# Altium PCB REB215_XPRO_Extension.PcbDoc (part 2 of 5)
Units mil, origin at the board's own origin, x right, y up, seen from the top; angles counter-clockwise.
Board outline 4055.74 x 2606 mil, 6 copper layers (Top Layer LF-signals, Signal Layer 1, Internal Plane 1, Mid-1, Mid-2, Bottom Layer LF-signals), stack 58.434 mil thick; 278 components, 292 nets, 1282 pads, 1177 vias.
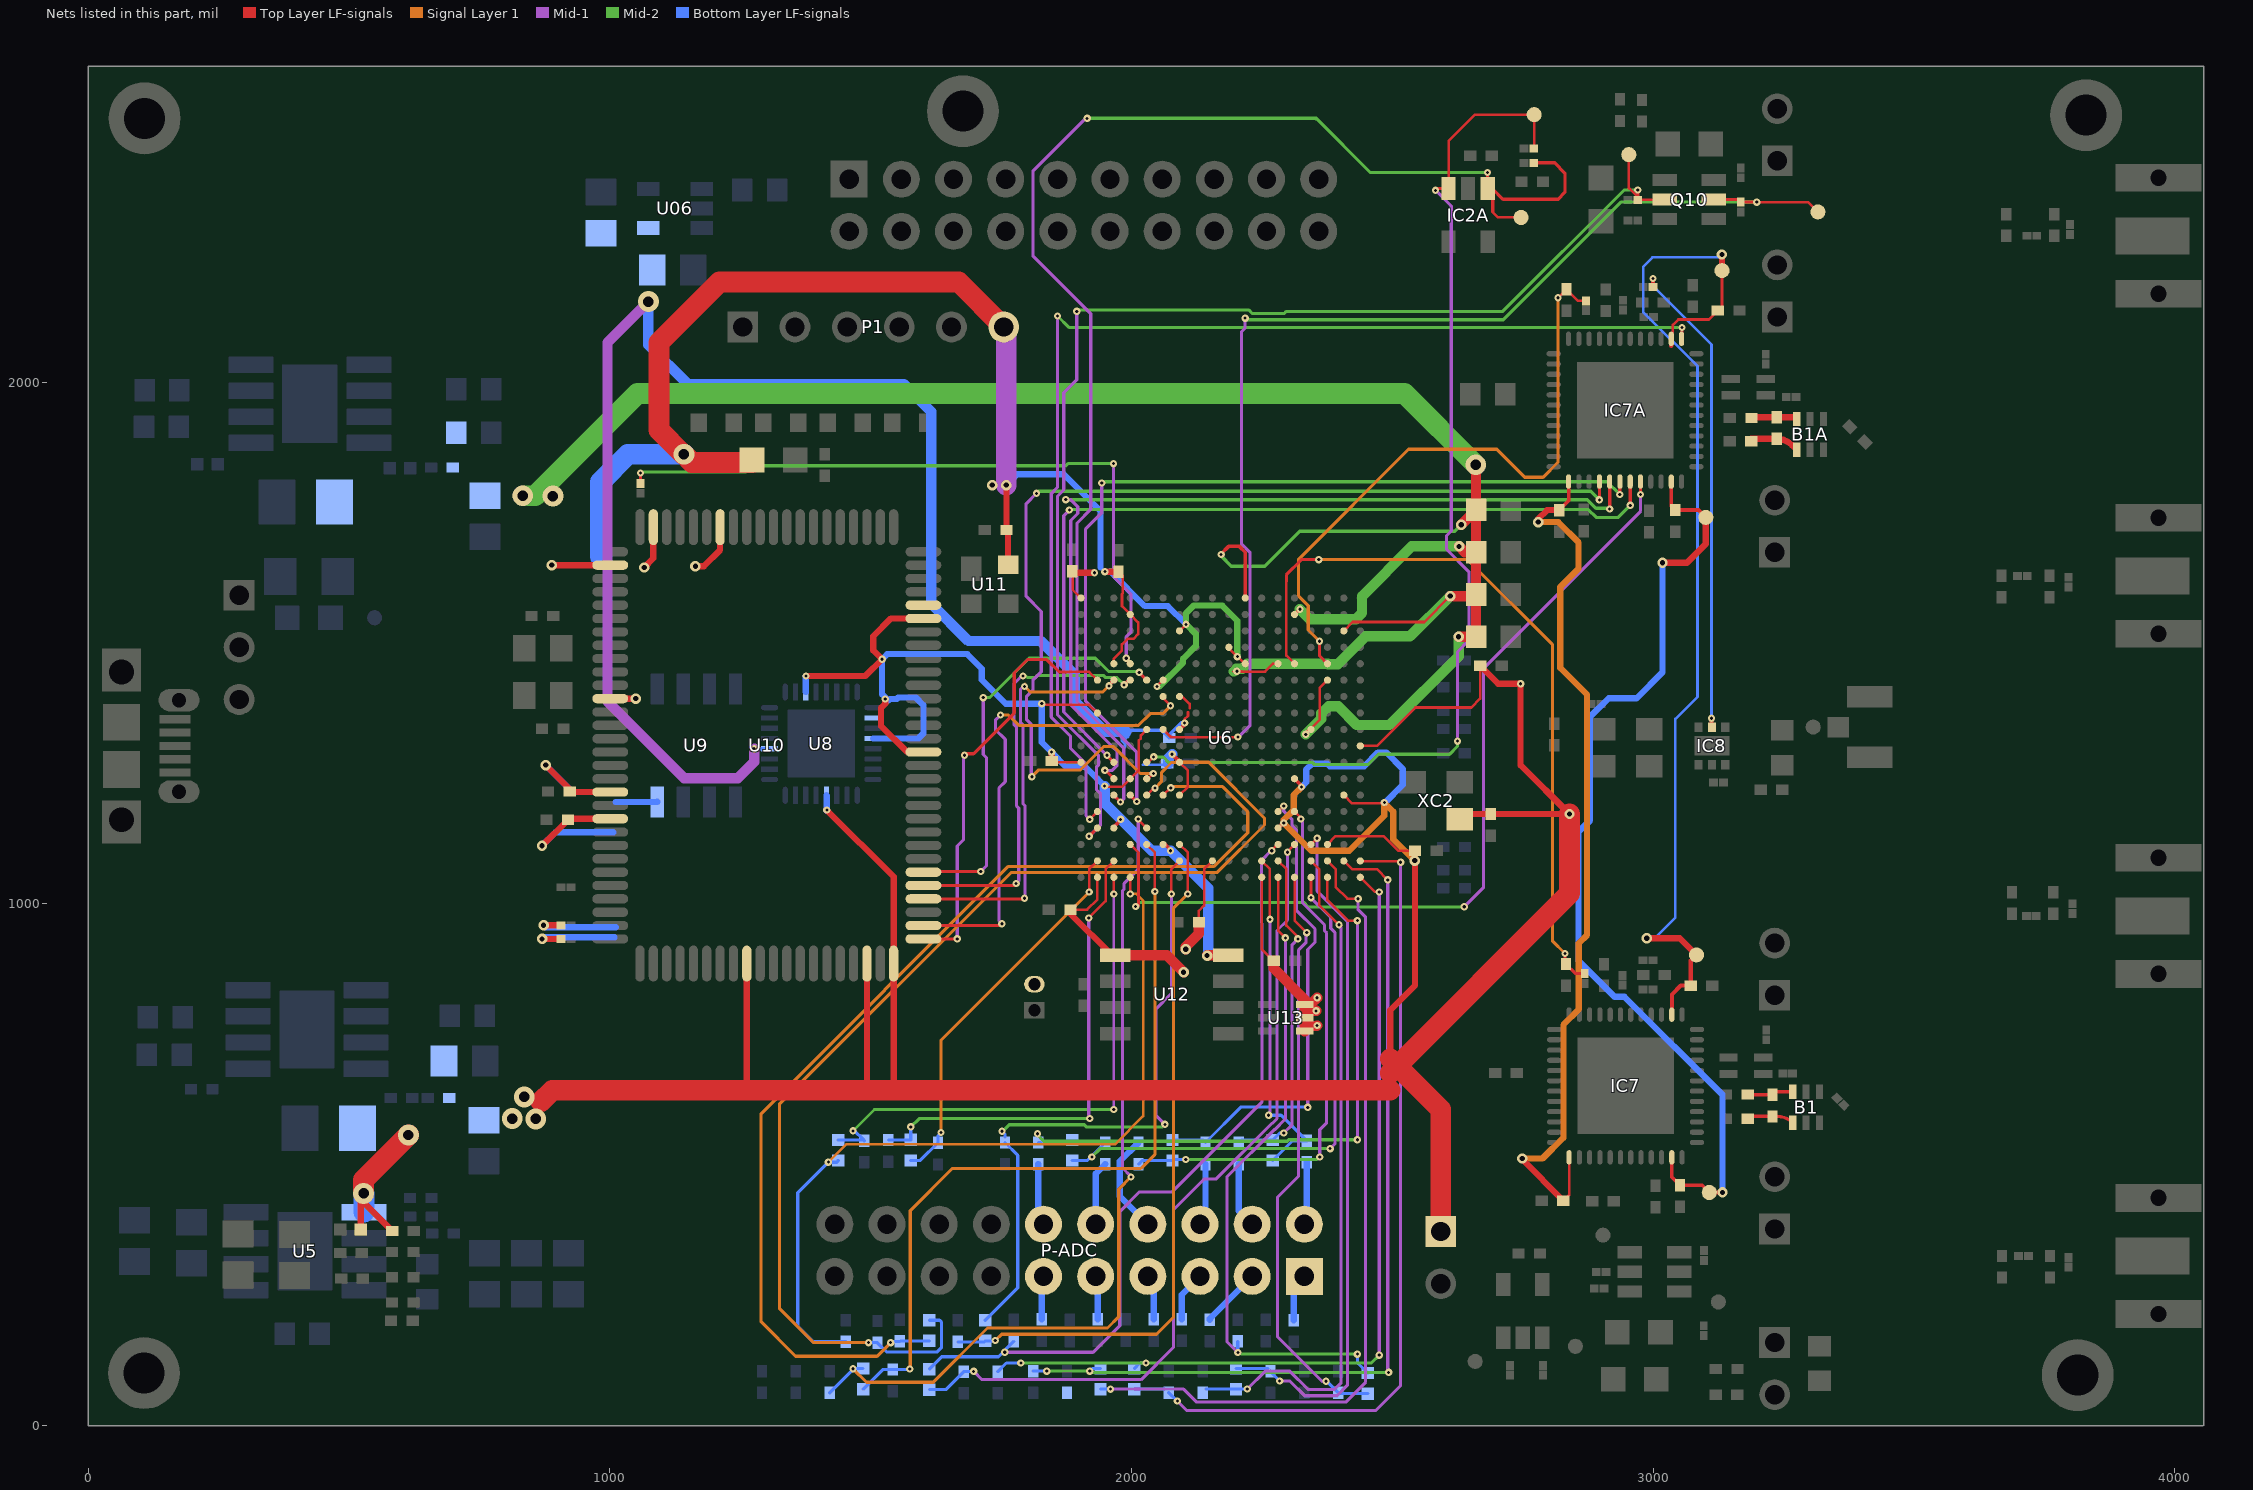
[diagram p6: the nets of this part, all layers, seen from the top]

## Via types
v1: diameter 20, hole 10, Top Layer LF-signals to Bottom Layer LF-signals, 660 vias
v2: diameter 14, hole 6, Top Layer LF-signals to Bottom Layer LF-signals, 470 vias
v3: diameter 40, hole 20, Top Layer LF-signals to Bottom Layer LF-signals, 46 vias
v4: diameter 12, hole 6, Top Layer LF-signals to Bottom Layer LF-signals, 1 vias

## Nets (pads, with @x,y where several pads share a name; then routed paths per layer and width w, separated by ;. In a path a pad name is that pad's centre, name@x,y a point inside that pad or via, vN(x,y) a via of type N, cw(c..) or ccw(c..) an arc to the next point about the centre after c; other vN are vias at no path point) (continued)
1V8: C48.1 C53.1 C54.1 L8.2 U06.4 U6.F12 U6.H12 U6.K12 U6.M12 U8.20 | length 3180.8
  Top Layer LF-signals w5: U6.F12@2092.18,1208.54 2107.93,1224.28 2107.93,1255.78 U6.H12@2092.18,1271.53 ; U6.M12@2092.18,1397.51 2097.28,1397.51 2111.41,1383.38 2111.41,1375.38 ; v2(2102,1347) 2102,1354.21 2108.38,1360.59 2108.38,1367.59
  Top Layer LF-signals w8: v2(2078,1287) 2092.18,1272.82 U6.H12@2092.18,1271.53 ; U6.K12@2092.18,1334.52 2102,1344.34 v2(2102,1347)
  Mid-1 w20: v3(1074,2154.53) 995.51,2076.04 995.51,1388.22 1142.57,1241.16 1245.34,1241.16 1276.67,1272.49 v2(1276.67,1297.46)
  Bottom Layer LF-signals w5: 1981.71,1319 1981.71,1312.49 1987.87,1306.33 ; 2022.2,1266.6 2068.66,1266.6 C53.1@2068.66,1269
  Bottom Layer LF-signals w6: v2(1276.67,1297.46) U8.20@1306.35,1297.46 ; 1987.87,1300.92 1987.87,1317.3 1992.99,1322.42 ; 1992.99,1319.93 1992.99,1322.42 ; 1996.05,1325.48 1992.99,1322.42 ; C53.1@2068.66,1266.1 C53.1@2068.66,1266.6 ; C54.1@2072.23,1318 2057.32,1332.91 1992.99,1332.91 1992.99,1322.42
  Bottom Layer LF-signals w7: C54.1@2072.46,1324.16 2095.3,1347 v2(2102,1347)
  Bottom Layer LF-signals w20: v3(1074,2154.53) 1074,2071.79 1149.08,1996.71 1563.07,1996.71 1616.09,1943.7 1616.09,1575.52 1687.58,1504.03 1826.41,1504.03 1890.92,1439.52 1890.92,1388.8 1949.45,1330.27 1989.78,1330.27 ; C53.1@2070.66,1269 2070.66,1279.66 v2(2078,1287)
2V5: C34.1 C35.1 C79.1 C80.1 C81.1 C82.1 L5.2 R18.2 U6.K4 U6.N3 U6.P6 U6.T2 U6.U5 U6.V8 | length 4925.4
  Top Layer LF-signals w5: v2@2195.67,1445.52 2211.51,1445.52 2211.83,1445.21 2255.99,1445.21 2271.29,1460.5 U6.P6@2281.15,1460.5 ; U6.K4@2342.01,1334.52 2361.25,1353.76 2361.25,1414.62 U6.N3@2375.64,1429.01 ; U6.T2@2407.14,1523.5 2424.14,1540.5 2561.45,1540.5 v1(2611,1590.05) ; v1@2629.03,1729.97 v1(2632,1727) 2632,1727.1 C79.1@2660.54,1755.63
  Top Layer LF-signals w7: v2(2172,1670) 2172,1671.2 2186.21,1685.41 2207.01,1685.41 2218.16,1674.25 U6.V8@2218.16,1586.49 ; U6.U5@2312.65,1554.99 2322.66,1565 v2(2323,1565) ; v2@2333,1325 v2(2334,1325) 2334,1326.51 2342.01,1334.52 U6.K4@2344.15,1334.52
  Top Layer LF-signals w20: v1(2611,1590.05) 2657.37,1590.05 C82.1@2660.54,1593.21 ; v1(2627,1512) C80.1@2660.54,1512 ; v1(2628,1685.45) 2639.03,1674.42 C81.1@2660.54,1674.42 ; v1(2632,1727) C79.1@2660.54,1755.54 ; C80.1@2658.54,1510 C80.1@2660.54,1512 ; v3(2660,1842) 2660,1846.93 2660.54,1847.47 C79.1@2660.54,1755.63 C79.1@2660.54,1755.54 ; C80.1@2660.54,1512 C82.1@2660.54,1593.21 ; C82.1@2660.54,1593.21 C81.1@2660.54,1674.42 ; C81.1@2660.54,1674.42 C79.1@2660.54,1755.54
  Mid-2 w7: v2(2172,1670) 2172,1666.8 2191.32,1647.48 2255.48,1647.48 2322.66,1714.66 2619.66,1714.66 v1(2632,1727) ; 2492,1340 2495,1343
  Mid-2 w20: v2@2195.67,1445.52 2201.24,1451.1 2212.49,1451.1 2221.9,1460.5 2376.03,1460.5 2377.39,1459.14 2395.62,1459.14 2449.48,1513 2533.95,1513 v1(2611,1590.05) ; v2(2323,1565) 2342,1546 2429.64,1546 2442,1558.36 2442,1577.23 2441.88,1577.35 2441.88,1589.77 2442,1589.89 2442,1590 2537.45,1685.45 v1(2628,1685.45) ; v2(2334,1325) 2334.11,1325 2364.16,1355.05 2364.16,1365.27 2377.89,1379 2396.11,1379 2432.11,1343 2495,1343 2627,1475 v1(2627,1512)
  Mid-2 w40: v3(833,1782.37) 856.37,1782.37 1052.85,1978.85 2523.15,1978.85 v3(2660,1842)
  other v2: 2202,1446
  other v3: 891,1781.78
3V3: C29.1 C30.1 C65.1 C66.1 C67.1 C68.1 C69.1 C70.1 C71.1 C72.1 C73.1 C74.1 C75.1 C76.1 D2A1.1 JP.1 L4.2 P1.6 P4.2 R001.2 R002.2 R015.2 R26.1 R27.1 U5.5 U6.A7 U6.A17 U6.B10 U6.C3 U6.C13 U6.D6 U6.D16 U6.F2 U6.G5 U6.G15 U6.H18 U6.J1 U6.K14 U6.L17 U6.N13 U6.P8 U6.P16 U6.R9 U6.T12 U6.U15 U6.V18 U8.4 U8.12 U8.27 U9.8 U10.2 U10.12 U10.19 U10.21 U10.39 U10.48 U10.50 U10.65 U10.75 U10.94 U10.99 U11.4 U12.1 U12.8 U13.4 U13.5 U13.6 XC2.4 | length 14448.6
  Top Layer LF-signals w5: v2@1826,1379.83 1827.93,1381.76 1918.95,1381.76 U6.L17@1934.7,1366.02 ; v2@1847,1291.58 v2(1847,1291) 1847.34,1290.66 1847.42,1290.58 1847.42,1274.08 C73.1@1847.34,1274 ; C73.1@1849.81,1271.53 U6.H18@1903.2,1271.53 ; C72.1@1883,989 1915,989 1934.7,1008.7 U6.A17@1934.7,1051.06 ; C74.1@1887.45,1636.94 1887.45,1602.24 U6.V18@1903.2,1586.49 ; v2(1948.59,1225.93) 1949.78,1224.74 1982.39,1224.74 U6.G15@1997.69,1240.03 2013.89,1256.23 2013.89,1312.89 2018,1317 2018,1323.33 U6.K14@2029.19,1334.52 ; U6.P16@1966.19,1460.5 1966.19,1470.37 1981.49,1485.66 1981.49,1497.43 1992.26,1508.2 2004.03,1508.2 2012.98,1517.16 2012.98,1539.7 U6.U15@1997.69,1554.99 1981.94,1570.74 1981.94,1594.16 1983.41,1595.62 1983.41,1628.26 C75.1@1975,1636.66 ; v2(2049,1417) 2049,1417.33 U6.N13@2060.68,1429.01 ; U6.T12@2092.18,1523.5 v2(2104.68,1536) ; C71.1@2129.34,965 2129.34,986.93 2139.42,997.01 2139.42,1066.8 U6.B10@2155.17,1082.55 ; v1(2145,901) v1@2145.45,901.45 ; U6.R9@2186.67,1492 2186.67,1490.08 2216.24,1460.5 U6.P8@2218.16,1460.5 ; U6.A7@2249.66,1051.06 2249.66,914 C68.1@2272.66,891 ; U6.C3@2375.64,1114.05 2391.39,1129.8 2483.56,1129.8 2511.26,1102.09 C76.1@2543.66,1102.09 ; U6.F2@2407.14,1208.54 2422.89,1192.79 2483.18,1192.79 v2(2484.72,1194.33) v2@2485,1194.61 ; U6.J1@2438.63,1303.02 2470.52,1303.02 2544.1,1376.6 2651.62,1376.6 2668.5,1393.47 C66.1@2668.5,1456.5
  Top Layer LF-signals w7: U6.D16@1966.19,1145.54 1966.19,1147.69 1979.22,1160.72 v2(1979.22,1162.07) ; U6.C13@2060.68,1114.05 2064.95,1114.05 2075,1104 v2(2075,1102) v2@2075.43,1102 ; U6.D6@2281.15,1145.54 2290.61,1155 v2(2292,1155) ; U6.G5@2312.65,1240.03 2326,1226.68 v2(2326,1224)
  Top Layer LF-signals w12: R26.1@522.69,376 v3@522.69,439.69 ; v3(528,445) 528,427.66 R27.1@582.66,373 ; v1(870,1111.63) C69.1@920,1161.63 ; v1(870.06,933) R002.2@906.65,933 ; v1(873,959) R001.2@906.65,959 ; v1(877,1266.1) 923,1220.1 C67.1@923,1215.4 ; v1@887.91,1648.5 v1(888.88,1649.47) U10.2@1000.8,1649.47 ; C69.1@921.62,1163.25 U10.21@1000.8,1163.25 ; C67.1@923.97,1214.43 U10.19@1000.8,1214.43 ; U10.12@1000.8,1393.57 v1(1049.57,1393.57) ; v1(1066,1645) 1083.48,1662.48 U10.99@1083.48,1722.31 ; v1(1164,1647.48) 1180.48,1647.48 1211.43,1678.43 U10.94@1211.43,1722.31 ; 1262.61,642.91 U10.39@1262.61,885.69 ; v2(1376,1437) 1490,1437 v2(1522,1469) 1505,1486 1505,1513.28 1538.83,1547.11 U10.75@1601.2,1547.11 ; v2(1416,1180) 1544.11,1051.89 U10.50@1544.11,885.69 1544.11,644.8 ; 1492.93,648.98 U10.48@1492.93,885.69 ; v2(1528,1393) 1528,1384 1520,1376 1520,1341 1569.8,1291.21 U10.65@1601.2,1291.21 ; v1@1757.44,1800.44 v1(1760,1803) 1760.34,1802.66 C65.1@1760.34,1716.79 ; U11.4@1763.43,1650.4 C65.1@1763.43,1713.7 ; C73.1@1847.34,1274 v2@1847.34,1290.66 ; C72.1@1883,989 1883,981.26 1962.81,901.45 U12.1@1968.83,901.45 ; C74.1@1886.73,1637.66 1884.07,1635 v2(1929,1635) ; v2@1949.09,1637.1 v2(1949,1637) 1949.34,1636.66 C75.1@1975,1636.66 ; 2496.09,676.1 2496.09,796.45 2543.66,844.02 C76.1@2543.66,1102.09 ; XC2.4@2639.05,1172.34 C70.1@2689,1172.34 v1(2839.66,1172.34) ; C66.1@2668.5,1456.5 2702.82,1422.18 v2(2746,1422.18) 2746,1266 v1(2839.66,1172.34) ; v1@2841,1171 v1(2839.66,1172.34)
  Top Layer LF-signals w20: U12.1@1968.83,901.45 2067.55,901.45 v1(2100,869) ; v1(2104,913) 2104,917.74 2129.34,943.08 C71.1@2129.34,965 ; v1@2145.45,901.45 U12.8@2185.36,901.45 ; C68.1@2272.66,891 2272.66,876.34 2332.36,816.64 U13.6@2332.36,807.36 ; U13.4@2332.36,756.18 2332.36,766 ; v2(2354,795) 2332.36,795 ; v2(2356,767) 2355,766 2332.36,766 ; v2(2356,820.2) 2343.16,807.36 U13.6@2332.36,807.36 ; 2332.36,766 U13.5@2332.36,781.77 2332.36,795 ; 2332.36,795 U13.6@2332.36,807.36
  Top Layer LF-signals w40: v3(528,445) 528,471 v3(614,557) ; 868,621 889.91,642.91 1262.61,642.91 2496.09,642.91 ; D2A1.1@1272.66,1851 1272.66,1846.51 1157.49,1846.51 v3(1142,1862) 1140.47,1862 1094,1908.47 1094,2076 1210,2192 1669,2192 P1.6@1755,2106 ; 2496.09,676.1 2839.66,1019.66 v1(2839.66,1172.34) ; 2496.09,703.1 2593,606.19 JP.1@2593,372
  Mid-1 w40: v1(1760,1803) P1.6@1760,2101
  Mid-2 w6: v2(2049,1417) v2@2053.74,1417
  Mid-2 w12: v2@2053.74,1417 2098.91,1462.17 2098.91,1470.22 2123.67,1494.99 2123.67,1517.01 v2(2104.68,1536) 2104.68,1557.78 2118.91,1572 2174,1572 2203,1543 v2(2203,1474)
  Signal Layer 1 w12: v2(2326,1224) 2310.91,1208.91 2310.91,1180.06 2292,1161.15 v2(2292,1155) 2345,1102 2417.54,1102 2484.72,1169.19 v2(2484.72,1194.33) 2502,1177.06 2502,1124 v1(2543,1083)
  Bottom Layer LF-signals w12: v3(528,445) 528,409.84 U5.5@528.66,409.18 ; v1(870,1111.63) 896.03,1137.66 1006.34,1137.66 ; v1(870.06,933) 872.97,935.91 1008.91,935.91 ; v1(873,959) 876.79,955.21 1011.21,955.21 ; v1(877,1266.1) 928.67,1214.43 1000.8,1214.43 ; 1011.54,1195.47 U9.8@1091,1195.47 U9.8@1091,1196 ; U8.27@1375.8,1406.31 1375.8,1436.8 v2(1376,1437) ; U8.12@1415.2,1208.31 1416,1207.51 v2(1416,1180) v2@1416,1178.4 ; U8.4@1504.35,1317.16 1591.65,1317.16 1601.2,1326.7 1601.2,1380.71 1586,1395.91 1553.17,1395.91 1550.26,1393 1537,1393 1534,1390 1522,1402 v2(1522,1469) 1532,1479 1685,1479 1713,1451 1713,1430 1759,1384 v2(1828,1384) 1828,1310 v2(1847,1291) 1847,1290.26 1874.26,1263 1911.52,1263 v2(1948.59,1225.93) ; v1(1760,1803) 1780.91,1823.91 1870.14,1823.91 1940.55,1753.5 1940.55,1645 ; 1958,1636.66 1960.08,1636.66 2025.74,1571 2069.68,1571 v2(2104.68,1536) ; v2(2326,1224) 2335.21,1233.21 2335.21,1257.83 2346.28,1268.91 2375.36,1268.91 2380.17,1264.1 2446.3,1264.1 2472.64,1290.43 2488.3,1290.43 2520,1258.74 2520,1228.3 2486.04,1194.33 v2(2484.72,1194.33)
  Bottom Layer LF-signals w20: v2(1948.59,1225.93) 1948.59,1192.69 v2(1979.22,1162.07) 2039.28,1102 v2(2075,1102) 2147,1030 v1@2147,903
  Bottom Layer LF-signals w40: U5.5@528.66,409.18 v3@528.66,444.34 ; 982,1666 982,1809 1035,1862 v3(1142,1862)
  other v1: 1733.09,1803
  other v3: 858,588 813,588.51 836,630
A-ID_SCL: IC2A.1 R102A.1 TP10A.1 U6.F16 | length 2691.2
  Top Layer LF-signals w5: IC2A.1@2682.66,2371.52 IC2A.1@2691.48,2371.52 ; v2(2682.66,2402) v2@2685.41,2404.75 ; 2692.57,2326.43 2703,2316 TP10A.1@2747,2316
  Top Layer LF-signals w6.15: U6.F16@1966.19,1208.54 1979.26,1195.47 v2(1979.04,1195.47) ; v2(2682.66,2402) IC2A.1@2682.66,2371.52 2682.66,2360.9 2692.57,2351 2692.57,2326.43 ; IC2A.1@2691.48,2371.52 2712,2351 2818,2351 2831,2364 2831,2401 2811.3,2420.7 R102A.1@2771.18,2420.7
  Mid-1 w6.15: v2(1915,2506) 1912.73,2506 1811.16,2404.43 1811.16,2242.44 1922,2131.6 1922,1756.35 1895.66,1730.01 1895.66,1388.01 1985.33,1298.33 1985.33,1201.76 v2(1979.04,1195.47)
  Mid-2 w6.15: v2(1915,2506) 2352.21,2506 2353.21,2505 2354.21,2506 2458.21,2402 v2(2682.66,2402)
A-ID_SDA: IC2A.3 R101A.1 TP11A.1 U6.H14 | length 2091.3
  Top Layer LF-signals w5: U6.H14@2029.19,1271.53 2032.12,1271.53 v2(2042.59,1282) ; IC2A.3@2607.86,2371.52 2608,2371.66 2608,2462.41 2658.59,2513 TP11A.1@2772,2513 R101A.1@2772,2449.19
  Top Layer LF-signals w6: v2@2586.52,2371.52 IC2A.3@2607.86,2371.52
  Mid-1 w6: v2(2583,2368) 2613.09,2337.91 2613.09,1714.9 2604,1705.81 2604,1680 2646.91,1637.1 2646.91,1505.17 2625,1483.26 v2(2625,1312)
  Mid-2 w6: v2(2042.59,1282) 2060.51,1282 2071.6,1270.91 2347.35,1270.91 2351.16,1267.1 2453.55,1267.1 2473.88,1287.43 2487.06,1287.43 2487.49,1287 2610,1287 2625,1302 v2(2625,1312)
A-IRQ: IC7A.40 U6.G14 | length 1998.3
  Top Layer LF-signals w5: U6.G14@2029.19,1240.03 2032.03,1240.03 v2(2042,1250)
  Top Layer LF-signals w6.14: v2(2897.03,1774.67) IC7A.40@2897.03,1809.66
  Mid-1 w6.14: v2(1809,1243.69) 1807,1245.69 1808.02,1246.72 1808.02,1344.24 1799.02,1353.25 1799.02,1397.95 1811.09,1410.03 ; 1811.02,1410.03 1811.02,1428.79 1827,1444.77 1827,1560.59 1798.02,1589.57 1798.02,1767.02 v2(1818,1787)
  Mid-2 w6.15: v2(1818,1787) 1821.98,1790.98 2880.72,1790.98 v2(2897.03,1774.67)
  Signal Layer 1 w6: 1902.38,1256.98 1947.41,1302 1965,1302 2017,1250 2022,1250
  Signal Layer 1 w6.14: v2(1809,1243.69) 1822.28,1256.98 1902.38,1256.98 ; 2022,1250 v2(2042,1250)
A-LED_POWER: Q10.5 R5A.1 TP12A.1 U6.K13 | length 2256.8
  Top Layer LF-signals w5: 2077,1320 2077.78,1319.22 2203.22,1319.22 v2(2204,1320) ; R5A.1@3162.96,2350.37 R5A.1@3168,2345.32 ; v2(3198.6,2345.32) 3297.1,2345.32 TP12A.1@3315.8,2326.62
  Top Layer LF-signals w6: U6.K13@2060.68,1334.52 2075.2,1320 2077,1320 ; Q10.5@3116.56,2350.37 R5A.1@3162.96,2350.37 ; R5A.1@3168,2345.32 v2(3198.6,2345.32)
  Mid-1 w6: v2@2204.75,1319.25 2226.91,1341.41 2226.91,1674.43 2210.81,1690.52 2210.81,2096.81 2218,2104 v2(2218,2123)
  Mid-2 w6: v2(2218,2123) 2221,2120 2712.86,2120 2938.18,2345.32 v2(3198.6,2345.32)
A-LED_TXRX: Q10.2 R1A.1 TP13A.1 U6.D17 | length 2427.8
  Top Layer LF-signals w5: TP13A.1@2953.37,2436.33 2953.37,2372.17 2970.6,2354.95 R1A.1@2970.6,2349.72 3021.42,2349.72 Q10.2@3022.07,2350.37
  Top Layer LF-signals w6: v2(1918.95,1129.8) U6.D17@1934.7,1145.54 ; R1A.1@2970.6,2354.95 v2(2970.6,2368.6)
  Mid-1 w6: v2(1895,2136) 1895,2004.79 1870.13,1979.93 1870.13,1793.63 1858.09,1781.59 1858.09,1749.04 1858.02,1748.96 1858.02,1363.04 1937.09,1283.96 1937.09,1266.59 1932.68,1262.18 1932.68,1219.34 1941,1211.02 1941,1151.85 v2(1918.95,1129.8)
  Mid-2 w6: v2(1895,2136) 1897.91,2138.91 2224.59,2138.91 2231.59,2131.91 2292.91,2131.91 2297,2136 2712.02,2136 2944.62,2368.6 v2(2970.6,2368.6)
A-MISO: IC7A.44 U6.C15 | length 1723.3
  Top Layer LF-signals w5: U6.C15@1997.69,1114.05 2013.44,1098.3 v2@2013.44,997.72
  Top Layer LF-signals w6: v2(2008,995) 2010.72,995 v2@2013.44,997.72
  Top Layer LF-signals w6.15: IC7A.44@2975.77,1809.66 2976,1809.43 v2(2976,1785) v2@2976.84,1785.84
  Mid-1 w6: v2(2638,994.65) 2675,1031.65 2675,1452 2976,1753 v2(2976,1785)
  Mid-2 w6: v2(2008,995) 2016,1003 2330.51,1003 2339.41,994.1 2638,994.1 v2(2638,994.65)
A-MOSI: IC7A.43 U6.H16 | length 1664.3
  Top Layer LF-signals w6.15: v2(1953,1285) 1953,1284.72 U6.H16@1966.19,1271.53 ; v2(2956.09,1764.09) IC7A.43@2956.09,1809.66
  Mid-1 w6.15: v2(1881,1755) 1870,1744 1870,1368 v2(1953,1285)
  Mid-2 w6.15: v2@1881,1756 2876.05,1756 2891.03,1741.03 2933.03,1741.03 v2(2956.09,1764.09)
A-R\S\T\N\: IC7A.13@3054.51,2083.28 U6.E17 | length 2251
  Top Layer LF-signals w5: v2@1918.95,1161.29 U6.E17@1934.7,1177.04
  Top Layer LF-signals w6: IC7A.13@3054.51,2083.28 v2(3055.51,2105)
  Mid-1 w6: v2(1858.23,2127) 1858.23,1798.56 1846.19,1786.52 1846.19,1753.97 1846.11,1753.89 1846.11,1358.11 1883.28,1320.94 1883.28,1297.99 1912.81,1268.46 1912.81,1169.32 v2(1920.07,1162.07)
  Mid-2 w6: v2(1858.23,2127) 1880.04,2105.19 3055.32,2105.19 v2(3055.51,2105)
A-S\S\_\S\E\L\: IC7A.42 U6.F15 | length 1713.3
  Top Layer LF-signals w6.15: U6.F15@1997.69,1208.54 v2@2010,1196.22 ; v2@2934,1783 v2(2936,1785) 2936,1809.26 IC7A.42@2936.4,1809.66
  Mid-1 w6.15: v2@1943,1808 v2(1943,1807) 1943,1749.98 1912.02,1719 1912.02,1388.69 2010.07,1290.65 v2(2010.07,1196.29)
  Mid-2 w6.15: v2@1943,1809.43 2911.57,1809.43 v2(2936,1785)
A-SCLK: IC7A.41 U6.G16 | length 1714
  Top Layer LF-signals w6.14: v2(2916.72,1757.01) IC7A.41@2916.72,1809.66
  Top Layer LF-signals w6.15: 1955.22,1251 U6.G16@1966.19,1240.03
  Mid-1 w6.15: v2(1874,1775) 1883.6,1775 1896.98,1761.62 1896.98,1748.38 1883.6,1735 1883.6,1381.6 1972,1293.21 1972,1265 1963,1256 v2(1949,1256)
  Mid-2 w6.15: v2(1874,1775) 2874.1,1775 2890.41,1758.69 2911.02,1758.69 2914.71,1755 v2(2916.72,1757.01)
AD1-N: C94.2 R73.2 U6.B12 | length 1244.5
  Top Layer LF-signals w5: v2(2076.43,1019.17) 2076.43,1066.8 U6.B12@2092.18,1082.55
  Mid-1 w6: v2@2064.48,577 v2(2064,577.48) 2046.44,595.04 2046.44,798.28 2076.43,828.27 v2(2076.43,1019.17)
  Mid-2 w6: v2(1752,564.31) 1752,563 1765.6,576.6 1909.41,576.6 1913.41,572.6 2059.12,572.6 v2(2064,577.48)
  Bottom Layer LF-signals w6: C94.2@1719.84,201.81 1782,263.97 1782,518.05 R73.2@1757.44,542.61 ; v2(1752,564.31) 1757.44,558.87 R73.2@1757.44,553.39
AD1-P: C94.1 R72.2 U6.C12 | length 1354.5
  Top Layer LF-signals w5: U6.C12@2092.18,1114.05 2107.93,1098.3 v2(2107.93,1019.17)
  Signal Layer 1 w6: v2(1739,163) 1751,175 2048,175 2080.27,207.27 2080.27,991.51 v2(2107.93,1019.17)
  Bottom Layer LF-signals w6: R72.2@1667.16,160.47 C94.1@1717.87,160.47 ; C94.1@1719.84,162.44 1738.44,162.44 v2(1739,163)
AD2-N: C96.2 R77.2 U6.B17 | length 733.1
  Top Layer LF-signals w5: v2(1918.95,1022.95) 1918.95,1066.8 U6.B17@1934.7,1082.55
  Signal Layer 1 w6: v2(1635,561.81) 1635,739 v2(1918.95,1022.95)
  Bottom Layer LF-signals w6: C96.2@1577,508.32 1595.32,508.32 R77.2@1629,542 1629,555.81 v2(1635,561.81)
AD2-P: C96.1 R76.2 U6.B16 | length 932.1
  Top Layer LF-signals w5: v2(1918,973) 1950.45,1005.45 1950.45,1066.8 U6.B16@1966.19,1082.55
  Mid-1 w6: v2(1918,973) 1918,590.57 v2(1920,588.51)
  Mid-2 w6: v2(1577,572.65) 1592.85,588.51 v2(1920,588.51)
  Bottom Layer LF-signals w6: R76.2@1534,547.34 C96.1@1576.65,547.34 ; C96.1@1577,547.69 v2(1577,572.65)
AD9-N: C95.2 R75.2 U6.F14 | length 2285.3
  Top Layer LF-signals w5: U6.F14@2029.19,1208.54 2029.95,1208.54 2043.41,1222 v2(2045,1222)
  Signal Layer 1 w6: v2(1496,159) 1391,159 1325,225 1325,616 1769,1060 2163.49,1060 2254.91,1151.41 2254.91,1164.59 2147.97,1271.53 2085.02,1271.53 2084.59,1271.1 2076.71,1271.1 2057.91,1252.29 2057.91,1234.91 v2(2045,1222)
  Bottom Layer LF-signals w6: v2(1496,159) R75.2@1513,159 1531.27,140.73 1627.03,140.73 1636.19,149.9 1636.19,197.81 1632.2,201.81 C95.2@1612.51,201.81
AD9-P: C95.1 R74.2 U6.F13 | length 2144.7
  Top Layer LF-signals w5: U6.F13@2060.68,1208.54 2074.71,1222.57 v2(2075.2,1222.57)
  Signal Layer 1 w6: v2(1538.38,159) 1512.38,133 1356,133 1290,199 1290,597.84 1764.07,1071.91 2158.56,1071.91 2222.91,1136.25 2222.91,1176.59 2174.68,1224.81 2077.45,1224.81 v2(2075.2,1222.57)
  Bottom Layer LF-signals w6: v2(1538.38,159) 1540.83,161.45 R74.2@1556,161.45 ; R74.2@1556.99,162.44 C95.1@1612.51,162.44
AD10-N: C97.2 R79.2 U6.A16 | length 1040.3
  Top Layer LF-signals w5: v2(1966.19,1019.17) U6.A16@1966.19,1051.06
  Mid-1 w5: v2@1966.19,606 v2(1966.19,1019.17)
  Mid-2 w5: v2(1466,565) 1507,606 v2(1966,606)
  Bottom Layer LF-signals w6.5: C97.2@1438.1,547.53 R79.2@1486.47,547.53 ; v2(1466,565) 1469,565 R79.2@1486.47,547.53 ; R79.2@1488,546 R79.2@1486.47,547.53
AD10-P: C97.1 R78.2 U6.A15 | length 1579.6
  Top Layer LF-signals w5: v2(1997.69,1019.17) U6.A15@1997.69,1051.06
  Signal Layer 1 w5: v2(1419,505) 1453,539 1968.12,539 2022.5,593.38 2022.5,1006.19 2009.52,1019.17 v2(1997.69,1019.17)
  Bottom Layer LF-signals w6.5: C97.1@1438.1,508.16 1434.94,505 v2(1419,505) 1360,446 1360,190 1389.53,160.47 R78.2@1452.51,160.47
AD12-N: C91.2 R67.2 U6.B6 | length 635.3
  Top Layer LF-signals w5: U6.B6@2281.15,1082.55 2296.9,1066.8 2296.9,958.66 2319,936.56 v2(2319,933)
  Mid-1 w6: v2(2292,561) 2308,577 2308,922 v2(2319,933)
  Bottom Layer LF-signals w6: R67.2@2210.82,547.53 C91.2@2270.95,547.53 2284.62,561.2 2291.8,561.2 v2(2292,561)
AD12-P: C91.1 R66.2 U6.B7 | length 668.5
  Top Layer LF-signals w5: U6.B7@2249.66,1082.55 2265.41,1066.8 v2(2265.41,970.41)
  Mid-1 w6: v2@2265.41,594.59 v2(2265.41,970.41)
  Bottom Layer LF-signals w6: v2(2263,595) 2287,595 R66.2@2336,546 2308.79,546 C91.1@2270.95,508.16
AD13-N: C92.2 R69.2 U6.E5 | length 1046.8
  Top Layer LF-signals w5: U6.E5@2312.65,1177.04 2325.69,1164 2325.69,1163.69 v2(2324.75,1162.75)
  Mid-1 w6: v2(2324.75,1162.75) 2328.09,1159.41 2328.09,1001.91 2370.19,959.81 2370.19,948.48 2374.19,944.48 2374.19,580.19 2361,567 v2(2361,515)
  Mid-2 w6: v2(2104,510) 2356,510 v2(2361,515)
  Bottom Layer LF-signals w6: R69.2@2013.7,501.27 2020.59,508.16 C92.2@2078.75,508.16 2080.59,510 v2(2104,510)
AD13-P: C92.1 R68.2 U6.E6 | length 906.5
  Top Layer LF-signals w5: U6.E6@2281.15,1177.04 v2(2292,1187.89)
  Mid-1 w6: v2(2292,1187.89) 2292,1177.49 2307.91,1161.59 2307.91,1150.29 2316.19,1142 2316.19,987.81 2351.91,952.1 2351.91,926.58 2338,912.67 v2(2338,610)
  Bottom Layer LF-signals w6: C92.1@2078.75,547.53 R68.2@2136.91,547.53 ; R68.2@2141.83,542.61 2210.22,611 v2@2338,611
AD14-N: C93.2 R71.2 U6.A3 | length 1222.4
  Top Layer LF-signals w5: U6.A3@2375.64,1051.06 2375.64,1007.36 2415.11,967.89 v2(2433.08,967.89)
  Mid-1 w6: v2(2433.08,548) v2(2433.08,967.89)
  Mid-2 w6: v2@1819.98,561.98 v2(1819.98,559.49) 1819.98,557 1831.89,545.1 2298.59,545.1 2301.49,548 v2(2433.08,548) ; v2@1820,562 v2@1820.48,561.52
  Bottom Layer LF-signals w6: R71.2@1821.5,542.61 C93.2@1881.63,542.61
AD14-P: C93.1 R70.2 U6.A4 | length 1083.8
  Top Layer LF-signals w5: v2(2344,1012) 2344,1019.02 2344.15,1019.17 U6.A4@2344.15,1051.06
  Mid-1 w6: v2(2344,1012) 2382.09,973.91 2382.09,953.41 2390,945.51 2390,539.91 v2@2381,530.91
  Mid-2 w6: v2(1924,515) 1939.91,530.91 v2(2380.91,530.91)
  Bottom Layer LF-signals w6: C93.1@1886.55,508.16 1915.19,508.16 R70.2@1949.64,542.61
AT_CLK0: C24.1 R12.1 U6.P5 | length 1433.4
  Top Layer LF-signals w5: 2296.9,1618.38 2296.9,1476.25 U6.P5@2312.65,1460.5
  Top Layer LF-signals w6: 2296.9,1618.38 2296.9,1630.9 2326,1660 v2(2358.95,1660) ; v2(2831,905) 2831,886.72 C24.1@2833,884.72 2851.37,866.35 R12.1@2869,866.35
  Signal Layer 1 w6: v2(2358.95,1660) 2644.3,1660 2806.83,1497.47 2806.83,929.17 v2(2831,905)
AT_CLK1: C24A.1 R12A.1 U6.P3 | length 1228.9
  Top Layer LF-signals w5: v2(2817.68,2162) C24A.1@2834,2178.32 2856.15,2156.18 R12A.1@2871.44,2156.18
  Top Layer LF-signals w6: v2@2360.53,1505.47 v2(2360.53,1503.61) 2360.53,1475.61 U6.P3@2375.64,1460.5
  Signal Layer 1 w6: v2(2360.53,1503.61) 2338.91,1525.24 2338.91,1571.59 2320.5,1589.99 2320.5,1661.05 2531.12,1871.67 2700.33,1871.67 2754,1818 2789.23,1818 2817.68,1846.45 v2(2817.68,2162)
AVDD0: C20.1 C20A.1 IC7.14@3035.83,787.82 IC7A.14@3034.83,2083.28 TP2.1 TP2A.1 | length 2027.4
  Top Layer LF-signals w5: IC7A.14@3034.83,2083.28 3037.91,2086.36 3037.91,2109.91 3048.41,2120.41 3106.91,2120.41 C20A.1@3124.15,2137.65 3132,2145.5 TP2A.1@3132,2214
  Top Layer LF-signals w7.99: IC7A.14@3034.83,2070.17 IC7A.14@3034.83,2083.28 ; IC7.14@3035.83,787.82 3036.04,788.04 3036.04,826.47 3052.92,843.34 C20.1@3072,843.34 3072,891.33
  Top Layer LF-signals w12: v1(2988,934.22) 3051.24,934.22 TP2.1@3083.07,902.4 ; TP2A.1@3132,2214 v1(3132,2245)
  Bottom Layer LF-signals w5: v1(2988,934.22) 3003.22,934.22 3042.7,973.7 3042.7,1354.57 3085.03,1396.9 3085.03,2030.97 2981,2135 2981,2221.43 2998.9,2239.33 3126.33,2239.33 v1(3132,2245)
AVDD1: C19.1 C19A.1 IC7.47 IC7A.47 TP1.1 TP1A.1 | length 1849
  Top Layer LF-signals w7: IC7A.47@3034.83,1809.66 3034.83,1762.97 C19A.1@3042.7,1755.1 3086.91,1755.1 TP1A.1@3101,1741 ; IC7.47@3035.83,514.2 3035.83,476.32 C19.1@3051.57,460.57 3094.02,460.57 TP1.1@3107.66,446.94 v1@3132.94,446.94 ; v1@3132.69,446.69 v1@3132.94,446.94 ; v1(3133,447) v1@3132.94,446.94
  Top Layer LF-signals w12: v1(3018,1654) 3065,1654 3101,1690 TP1A.1@3101,1741
  Bottom Layer LF-signals w12: v1(3018,1654) 3018,1444 2968.32,1394.32 2914.76,1394.32 2879,1358.56 2879,1160 2857,1138 2857,891 2926,822 2945.03,822 3133,634.03 v1(3133,447)
B1_N: B1.3 C12.2 L3.1 | length 92.8
  Top Layer LF-signals w6.5: C12.2@3181.18,634.83 3181.18,634 L3.1@3229,634 3229,639.66 B1.3@3267.52,639.66
B1_P: B1.4 C2.2 L3.2 | length 93.8
  Top Layer LF-signals w6.5: C2.2@3181.18,588.37 3181.18,592.66 L3.2@3229,592.66 3238.42,592.66 cw(c3238.42,551.52) B1.4@3267.52,580.61
B1A-N: B1A.3 C12A.2 L3A.1 | length 90.4
  Top Layer LF-signals w12: C12A.2@3188.53,1933 L3A.1@3237,1933 3275.41,1933 B1A.3@3275.41,1929.53
B1A-P: B1A.4 C02A.2 L3A.2 | length 94.1
  Top Layer LF-signals w12: C02A.2@3188.34,1891.66 L3A.2@3237,1891.66 cw(c3237,1850.09) 3266.4,1879.49 B1A.4@3275.41,1870.47
CK-A0: P-ADC.1 R65.2 | length 63.9
  Bottom Layer LF-signals w12: R65.2@2311.1,201.81 P-ADC.1@2311.1,265.69
CK-A1: P-ADC.3 R64.2 | length 116.9
  Bottom Layer LF-signals w12: R64.2@2150.11,202.79 2150.11,204.7 P-ADC.3@2231.41,286
CK-A2: P-ADC.5 R63.2 | length 96.7
  Bottom Layer LF-signals w12: R63.2@2096.45,203.77 2096.45,251.04 P-ADC.5@2131.41,286
CK-A3: P-ADC.7 R62.2 | length 70.8
  Bottom Layer LF-signals w12: R62.2@2042.79,203.77 P-ADC.7@2042.79,274.62
CK-A4: P-ADC.9 R61.2 | length 78.2
  Bottom Layer LF-signals w12: R61.2@1935.47,203.77 P-ADC.9@1935.47,281.95
CK-A5: P-ADC.11 R60.2 | length 79
  Bottom Layer LF-signals w12: R60.2@1828.14,203.77 P-ADC.11@1828.14,282.73
CK-A6: P-ADC.2 R66.1 | length 114.1
  Bottom Layer LF-signals w12: P-ADC.2@2336,390.59 R66.1@2336,504.66
CK-A7: P-ADC.4 R67.1 | length 89.8
  Bottom Layer LF-signals w12: 2205.9,411.51 R67.1@2205.9,501.27
CK-A8: P-ADC.6 R68.1 | length 104.8
  Bottom Layer LF-signals w12: P-ADC.6@2141.83,396.42 R68.1@2141.83,501.27
CK-A9: P-ADC.8 R69.1 | length 193.9
  Bottom Layer LF-signals w12: R69.1@2013.7,542.61 1977.58,506.49 1977.58,439.83 P-ADC.8@2031.41,386
CK-A10: P-ADC.10 R70.1 | length 122.8
  Bottom Layer LF-signals w12: P-ADC.10@1931.41,386 1931.41,483.05 R70.1@1949.64,501.27
CK-A11: P-ADC.12 R71.1 | length 105.4
  Bottom Layer LF-signals w12: P-ADC.12@1821.5,395.91 R71.1@1821.5,501.27
CK-AN0-N: C85.2 R46.1 U6.C5 | length 1587.8
  Top Layer LF-signals w5: v2(2299,1099) 2299,1100.4 U6.C5@2312.65,1114.05
  Mid-1 w6: v2(1697.49,104) 1713.49,88 2018.49,88 2080.27,149.78 2080.27,413.27 2140,473 2162.74,473 2268.84,579.1 2269.59,579.1 2279,588.51 2279,949 2299,969 v2(2299,1099)
  Bottom Layer LF-signals w6: C85.2@1612.64,68.91 1644.16,68.91 R46.1@1678.61,103.36 v2@1696.86,103.36
CK-AN0-P: C85.1 R40.1 U6.C6 | length 1515.1
  Top Layer LF-signals w5: v2(2269,1102) 2269,1103.5 2281.15,1115.65 U6.C6@2281.15,1114.05
  Mid-1 w6: v2(1757,140.45) 1926.62,140.45 1977.52,191.35 1977.52,410.02 2015.5,448 2078,448 2250,620 2250,962.82 2249.5,963.32 2249.5,1084 2267.5,1102 v2(2269,1102)
  Bottom Layer LF-signals w6: C85.1@1612.64,108.28 1636.35,132 1745.03,132 R40.1@1774.48,161.45
CK-AN1-N: C86.2 R47.1 U6.A5 | length 1131.2
  Top Layer LF-signals w5: U6.A5@2312.65,1051.06 2312.65,968.35 v2(2336,945)
  Mid-1 w6: v2(2336,945) 2332.75,941.75 2334.91,939.59 2334.91,926.41 2320.42,911.93 2320.42,478.42 2280,438 2280,170.15 2365.15,85 v2(2373,85)
  Bottom Layer LF-signals w6: v2(2373,85) 2374.45,85 R47.1@2396.43,63.03 ; R47.1@2398.14,61.32 C86.2@2453,61.32
CK-AN1-P: C86.1 R41.1 U6.A6 | length 1273.5
  Top Layer LF-signals w5: U6.A6@2281.15,1051.06 2281.15,948.85 v2(2295,935)
  Mid-1 w6: v2(2204,140.23) 2183,161.23 2183,476.42 2273.77,567.19 2274.52,567.19 2295,587.67 v2(2295,935)
  Mid-2 w6: v2(2204,140.23) 2204,144 2211,137 v2(2433.08,137)
  Bottom Layer LF-signals w6: v2@2203.77,140.45 R41.1@2203.77,161.45 ; v2(2433.08,137) 2433.08,120.61 2435.69,118 ; 2435.81,118 2435.69,118 ; C86.1@2453,100.69 2435.69,118
CK-AN2-N: C87.2 R48.1 U6.B4 | length 1317.3
  Top Layer LF-signals w5: U6.B4@2344.15,1082.55 2359.89,1066.8 2359.89,998.11 v2(2398,960)
  Mid-1 w6: v2(2222,70) 2256.36,104.36 2303.64,104.36 2338.91,69.1 2389.08,69.1 2401.91,81.92 2401.91,956.1 v2(2398,960)
  Bottom Layer LF-signals w6: R48.1@2143.38,69.91 C87.2@2200.49,69.91 2221.91,69.91 v2(2222,70)
CK-AN2-P: C87.1 R42.1 U6.C4 | length 1326.7
  Top Layer LF-signals w5: U6.C4@2344.15,1114.05 v2(2356,1125.9)
  Mid-1 w6: v2(2284,85.54) 2303.65,85.54 2332,57.19 2394.01,57.19 2414,77.18 2414,965 2413.91,965.1 2413.91,966.59 2356,1024.49 v2(2356,1125.9)
  Bottom Layer LF-signals w6: C87.1@2200.49,109.28 R42.1@2261.54,109.28 ; R42.1@2266.46,104.36 2266.46,103.08 v2(2284,85.54)
CK-AN3-N: C88.2 R49.1 U6.A1 | length 1707.5
  Top Layer LF-signals w5: U6.A1@2438.63,1051.06 2466.69,1023 v2(2475,1023)
  Mid-1 w6: v2(2475,135) v2(2475,1023)
  Mid-2 w6: v2@1788,120.27 2027.73,120.27 v2(2028,120) 2460,120 v2(2475,135)
  Bottom Layer LF-signals w6: R49.1@1743.59,103.36 1760.23,120 v2(1788,120) ; C88.2@2005.53,109.28 2016.25,120 v2(2028,120)
CK-AN3-P: C88.1 R43.1 U6.B1 | length 1618.4
  Top Layer LF-signals w5: U6.B1@2438.63,1082.55 2439.59,1081.6 v2@2516,1081.6
  Mid-1 w6: v2(2088,47) 2106,29 2468.21,29 2516,76.8 v2(2516,1080)
  Bottom Layer LF-signals w6: C88.1@2005.53,69.91 R43.1@2064.61,69.91 ; R43.1@2071.5,63.03 2087.53,47 v2(2088,47)
CK-AN4-N: C89.2 R50.1 U6.B2 | length 1748.1
  Top Layer LF-signals w5: U6.B2@2407.14,1082.55 2422.89,1066.8 2470.52,1066.8 v2(2491.23,1046.1)
  Mid-1 w6: v2@2491.23,102.1 v2(2491.23,1046.1)
  Mid-2 w6: v2(1837.64,104.36) v2(1920.07,104.36) 1922.34,102.1 2492.91,102.1 v2(2493,102)
  Bottom Layer LF-signals w6: R50.1@1811.56,104.36 v2(1837.64,104.36) ; v2(1920.07,104.36) 1924.99,109.28 C89.2@1940.55,109.28
CK-AN4-P: C89.1 R44.1 U6.B3 | length 1576.3
  Top Layer LF-signals w5: U6.B3@2375.64,1082.55 2391.39,1066.8 2391.39,1032.61 2414,1010 v2(2434.5,1010)
  Mid-1 w6: v2(1960,69.91) 2100.09,69.91 2125,45 2410.69,45 2448.98,83.29 2448.98,974.47 2434.5,988.96 v2(2434.5,1010)
  Bottom Layer LF-signals w6: C89.1@1940.55,69.91 v2(1960,69.91)
CK-AN5-N: C90.2 R51.1 U6.C14 | length 1527.4
  Top Layer LF-signals w5: U6.C14@2029.19,1114.05 2044.93,1098.3 v2(2044.93,1024) v2@2044.93,1019.17
  Signal Layer 1 w6: v2(1575,108.32) 1576,109.32 1576,412 1657.03,493.03 2018.62,493.03 2044.93,519.35 v2(2044.93,1024)
  Bottom Layer LF-signals w6: C90.2@1485.65,69.91 1523.08,107.34 R51.1@1542.43,107.34 v2@1574.02,107.34
CK-AN5-P: C90.1 R45.1 U6.D14 | length 1665.1
  Top Layer LF-signals w5: v2(2013,1163) 2013,1161.91 2029.19,1145.72 U6.D14@2029.19,1145.54
  Mid-1 w6: v2(1998.94,476.55) 1998.94,477.65 1982.69,493.91 1982.69,1025.38 1986,1028.69 1986,1039.37 2013,1066.37 v2(2013,1163)
  Signal Layer 1 w6: v2(1466,109) 1492,83 1620,83 1724,187 1953.93,187 1975.75,208.82 1975.75,453.36 v2(1998.94,476.55)
  Bottom Layer LF-signals w6: R45.1@1421.65,63.03 v2@1467.91,109.28 ; v2(1466,109) 1466.28,109.28 v2@1467.91,109.28 ; C90.1@1485.65,109.28 v2@1467.91,109.28
CLK1: C25A.1 IC8.2 | length 922.4
  Top Layer LF-signals w8.27: C25A.1@2999.7,2183 v2(2999.7,2198.81) ; v2(3112,1356) 3112,1339.65 IC8.2@3112.63,1339.02
  Bottom Layer LF-signals w5: v2(2999.7,2198.81) 2999.7,2184.3 3112,2072 v2(3112,1356)
CTL0: U6.N16 U10.54 | length 799.6
  Top Layer LF-signals w6: U10.54@1601.2,1009.71 1793.71,1009.71 v2(1795,1011) ; v2@1957.19,1420 U6.N16@1966.19,1429.01
  Mid-1 w6: v2(1795,1011) 1795.81,1011.81 1795.81,1188.52 1791.81,1192.52 1791.81,1343.52 1787.04,1348.29 1787.04,1411.17 v2@1795.93,1420.07
  Signal Layer 1 w6: v2@1796.09,1421.1 1795,1420 v2(1795,1417) 1805.73,1406.27 1945.27,1406.27 v2(1957,1418)
CTL1: U6.N15 U10.55 | length 808.1
  Top Layer LF-signals w6: U10.55@1601.2,1035.3 v2@1775.3,1035.3 ; v2(1986,1420) 1995.01,1429.01 U6.N15@1997.69,1429.01
  Mid-1 w6: v2(1779,1039) 1783.91,1043.91 1783.91,1183.59 1779.91,1187.59 1779.91,1338.59 1775.13,1343.36 1775.13,1422.63 1788.41,1435.91 1789.28,1435.91 1791.91,1438.53 1792,1438.44 v2(1792,1437)
  Mid-2 w6: v2(1792,1437) 1797.53,1437 1800.44,1434.1 1815.59,1434.1 1819.58,1438.08 1946.24,1438.08 1950.41,1433.91 1972.09,1433.91 v2(1986,1420)
CTL2: U6.N14 U10.56 | length 814.6
  Top Layer LF-signals w6: U10.56@1601.2,1060.89 1602.31,1062 v2(1711,1062) ; v2@2016.03,1446.14 2016.03,1442.16 U6.N14@2029.19,1429.01
  Mid-1 w6: v2(1711,1062) 1721.81,1072.81 1721.81,1280.58 1716,1286.39 v2(1716,1395.41)
  Mid-2 w6: v2(1716,1395.41) 1727.92,1395.41 1803.51,1471 1930.83,1471 1956.02,1445.81 2013.19,1445.81 v2(2015,1444)
CTL3: U6.N17 U10.51 | length 816.3
  Top Layer LF-signals w5: 1880,1444.76 1918.95,1444.76 U6.N17@1934.7,1429.01
  Top Layer LF-signals w6: U10.51@1601.2,932.94 v2@1665.94,932.94 ; v2@1677,1288 1697.49,1288 1775.34,1365.85 1775.34,1442.83 1800.82,1468.31 1837.55,1468.31 1861.11,1444.76 1880,1444.76
  Mid-1 w6: v2(1666,933) 1666,1111 1678.09,1123.1 1678.09,1283.1 v2(1680,1285)
CTL4: U6.M13 U10.52 | length 940.4
  Top Layer LF-signals w5: U6.M13@2060.68,1397.51 2060.68,1394.32 v2(2075,1380)
  Top Layer LF-signals w6: U10.52@1601.2,958.53 v2@1748.05,958.53 ; U6.M13@2060.68,1397.51 U6.M13@2061.51,1397.51
  Mid-1 w6: v2(1749,1362) 1739.04,1352.04 1739.04,1334.46 1758,1315.51 1758,1234.49 1746.09,1222.59 1746.09,967.43 v2(1751.52,962)
  Signal Layer 1 w6: v2(1749,1362) 1764.33,1362 1784.12,1342.2 2008.79,1342.2 ; 2009,1342.41 2008.79,1342.2 ; v2(2075,1380) 2059.91,1364.91 2036.2,1364.91 2013.5,1342.2 2008.79,1342.2
CTL5: U10.76
CTLS: U8.2
DVDD: C18.1 C18A.1 IC7.37 IC7A.37 | length 1701.3
  Top Layer LF-signals w5: C18.1@2828,431 2838.98,441.98 IC7.37@2838.98,514.2
  Top Layer LF-signals w7: C18A.1@2820,1755 2837.98,1772.98 IC7A.37@2837.98,1809.66
  Top Layer LF-signals w12: v1(2749,512) 2748.8,511.8 2748.8,510.2 C18.1@2828,431 ; v1(2780,1732) 2780,1738.28 2796.72,1755 C18A.1@2820,1755
  Signal Layer 1 w12: v1(2749,512) 2788,512 2828,552 2828,768 2857.66,797.66 2857.66,924.66 2873.44,940.44 2873.44,1401 2822,1452.44 2822,1607.6 2857,1642.6 2857,1693 2818,1732 v1(2780,1732)
FXCLK: R018.2 U6.P15 | length 1337.1
  Top Layer LF-signals w6: R018.2@1059,1806 v2(1059,1826) ; v2@1988.19,1470 U6.P15@1997.69,1460.5
  Mid-1 w6: v2(1965.45,1844) 1965.45,1627.52 1998.91,1594.06 1998.91,1520.91 1990,1512 v2(1990,1471)
  Mid-2 w6: v2(1059,1826) v2@1059,1828 ; v2@1061,1828 1261.16,1828 1273.16,1840 1874,1840 1878,1844 v2(1965.45,1844)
